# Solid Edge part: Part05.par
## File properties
Author: Robert a Rhodes jr
Template: Normal.par
Last saved by: Cadcim
Revision: 2
Application: Solid Edge
Accuracy: 0.99
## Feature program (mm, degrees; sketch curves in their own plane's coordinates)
body "unnamed Body 1"
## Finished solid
Body 1: solid body, 82 faces, 169 edges, 90 vertices.
  Faces by surface: cylinder 44, plane 27, torus 6, spline 3, cone 2
  Edges by curve: circle 64, ellipse 44, line 26, intersection 24, curve on surface 11
Bounding box of the edges (mm; curved faces can reach further): 3403.600 x 1854.200 x 1930.410, from (-1701.8, 0, -965.2014) to (1701.8, 1854.2, 965.2088).
Cylindrical faces by radius (mm): R63.5 x26, R76.2 x4, R95.25 x4, R317.5 x4, R342.9 x3, R558.8 x1, R965.2 x2
Conical faces (half-angle, radius in mm at the cone's reference point): 15 deg R654.5026 x1, 16.46 deg R711.4955 x1
Toroidal faces (ring radius, tube radius in mm): R408.1559 r101.6 x1, R609.6 r50.8 x1, R851.7802 r50.8 x1, R889 r76.2 x2, R983.9044 r127 x1
Planar faces by outward normal: +y 20, +z 1, -y 5, -z 1
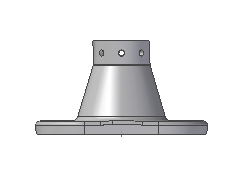
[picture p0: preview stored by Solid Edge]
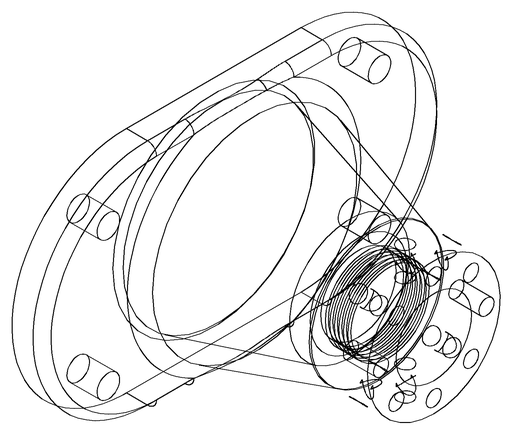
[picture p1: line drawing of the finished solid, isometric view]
